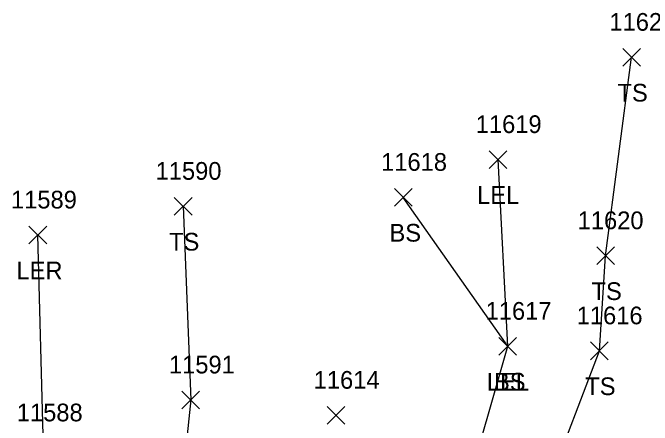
# Model space of a CAD drawing. Extents: x 1475671 to 1477951, y 592661 to 593821.
# Drawn here: x 1476894.9 to 1476967.1, y 593600.2 to 593646.7 of the extents above; entities that cross this region are included whole.
import ezdxf

# ---------------------------------------------------------------- set-up
doc = ezdxf.new("R2010")
doc.units = 0
for name, color, linetype in [('L_A', 7, 'Continuous'), ('L_I', 7, 'Continuous'), ('L_TIC', 7, 'Continuous'), ('LARO', 7, 'Continuous'), ('LELB', 7, 'Continuous')]:
    doc.layers.add(name, color=color, linetype=linetype)

msp = doc.modelspace()

# ---------------------------------------------------------------- linework, layer by layer
at = {"layer": 'L_TIC'}
for points in [[(1476963.781, 593640.714), (1476965.781, 593642.714)], [(1476965.781, 593640.714), (1476963.781, 593642.714)], [(1476948.698, 593629.16), (1476950.698, 593631.16)], [(1476950.698, 593629.16), (1476948.698, 593631.16)], [(1476938.004, 593624.896), (1476940.004, 593626.896)], [(1476940.004, 593624.896), (1476938.004, 593626.896)], [(1476913.151, 593623.884), (1476915.151, 593625.884)], [(1476915.151, 593623.884), (1476913.151, 593625.884)], [(1476896.744, 593620.639), (1476898.744, 593622.639)], [(1476898.744, 593620.639), (1476896.744, 593622.639)], [(1476960.851, 593618.301), (1476962.851, 593620.301)], [(1476962.851, 593618.301), (1476960.851, 593620.301)], [(1476949.804, 593608.072), (1476951.804, 593610.072)], [(1476951.804, 593608.072), (1476949.804, 593610.072)], [(1476949.804, 593608.072), (1476951.804, 593610.072)], [(1476951.804, 593608.072), (1476949.804, 593610.072)], [(1476960.143, 593607.558), (1476962.143, 593609.558)], [(1476962.143, 593607.558), (1476960.143, 593609.558)], [(1476914.005, 593602.007), (1476916.005, 593604.007)], [(1476916.005, 593602.007), (1476914.005, 593604.007)], [(1476930.392, 593600.279), (1476932.392, 593602.279)], [(1476932.392, 593600.279), (1476930.392, 593602.279)]]:
    msp.add_lwpolyline(points, dxfattribs=at)
at = {"layer": 'LARO'}
for points in [[(1476929.852, 593528.262), (1476924.138, 593529.667), (1476933.035, 593537.501), (1476942.924, 593551.204), (1476947.204, 593570.892), (1476944.959, 593580.389), (1476945.97, 593592.107), (1476950.804, 593609.072), (1476949.698, 593630.16)], [(1476906.352, 593515.376), (1476905.861, 593533.595), (1476901.814, 593550.148), (1476902.505, 593566.094), (1476902.278, 593584.047), (1476898.393, 593597.596), (1476897.744, 593621.639)]]:
    msp.add_lwpolyline(points, dxfattribs=at)
at = {"layer": 'LELB'}
for points in [[(1476933.035, 593537.501), (1476926.638, 593540.652), (1476928.888, 593555.31), (1476934.635, 593563.955), (1476944.959, 593580.389), (1476955.246, 593593.06), (1476961.143, 593608.558), (1476961.851, 593619.301), (1476964.781, 593641.714)], [(1476950.804, 593609.072), (1476939.004, 593625.896)], [(1476914.151, 593624.884), (1476915.005, 593603.007), (1476912.924, 593582.923), (1476912.083, 593555.201), (1476913.693, 593535.901), (1476915.35, 593522.294)]]:
    msp.add_lwpolyline(points, dxfattribs=at)

# ---------------------------------------------------------------- texts
at = {"layer": 'L_A'}
for s, p in [('TS', (1476963.19, 593636.714)), ('LEL', (1476947.336, 593625.16)), ('BS', (1476937.445, 593620.896)), ('TS', (1476912.561, 593619.884)), ('LER', (1476895.327, 593616.639)), ('TS', (1476960.26, 593614.301)), ('LEL', (1476948.442, 593604.072)), ('BS', (1476949.245, 593604.072)), ('TS', (1476959.552, 593603.558))]:
    msp.add_text(s, height=2, dxfattribs=at).set_placement(p)
at = {"layer": 'L_I'}
for s, p in [('11621', (1476962.277, 593644.714)), ('11619', (1476947.186, 593633.16)), ('11618', (1476936.5, 593628.896)), ('11590', (1476911.041, 593627.884)), ('11589', (1476894.713, 593624.639)), ('11620', (1476958.693, 593622.301)), ('11617', (1476948.3, 593612.072)), ('11617', (1476948.3, 593612.072)), ('11616', (1476958.584, 593611.558)), ('11591', (1476912.548, 593606.007)), ('11614', (1476928.889, 593604.279)), ('11588', (1476895.37, 593600.596)), ('11588', (1476895.37, 593600.596))]:
    msp.add_text(s, height=2, dxfattribs=at).set_placement(p)

doc.saveas('drawing.dxf')
